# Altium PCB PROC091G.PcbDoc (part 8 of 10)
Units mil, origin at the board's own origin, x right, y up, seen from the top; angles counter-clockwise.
Board outline 4538.11 x 994.94 mil, 8 copper layers (Top Layer, GND1, Sig1, PWR1, PWR2, Sig2, GND2, Bottom Layer), stack 59.155 mil thick; 446 components, 329 nets, 5050 pads, 868 vias.
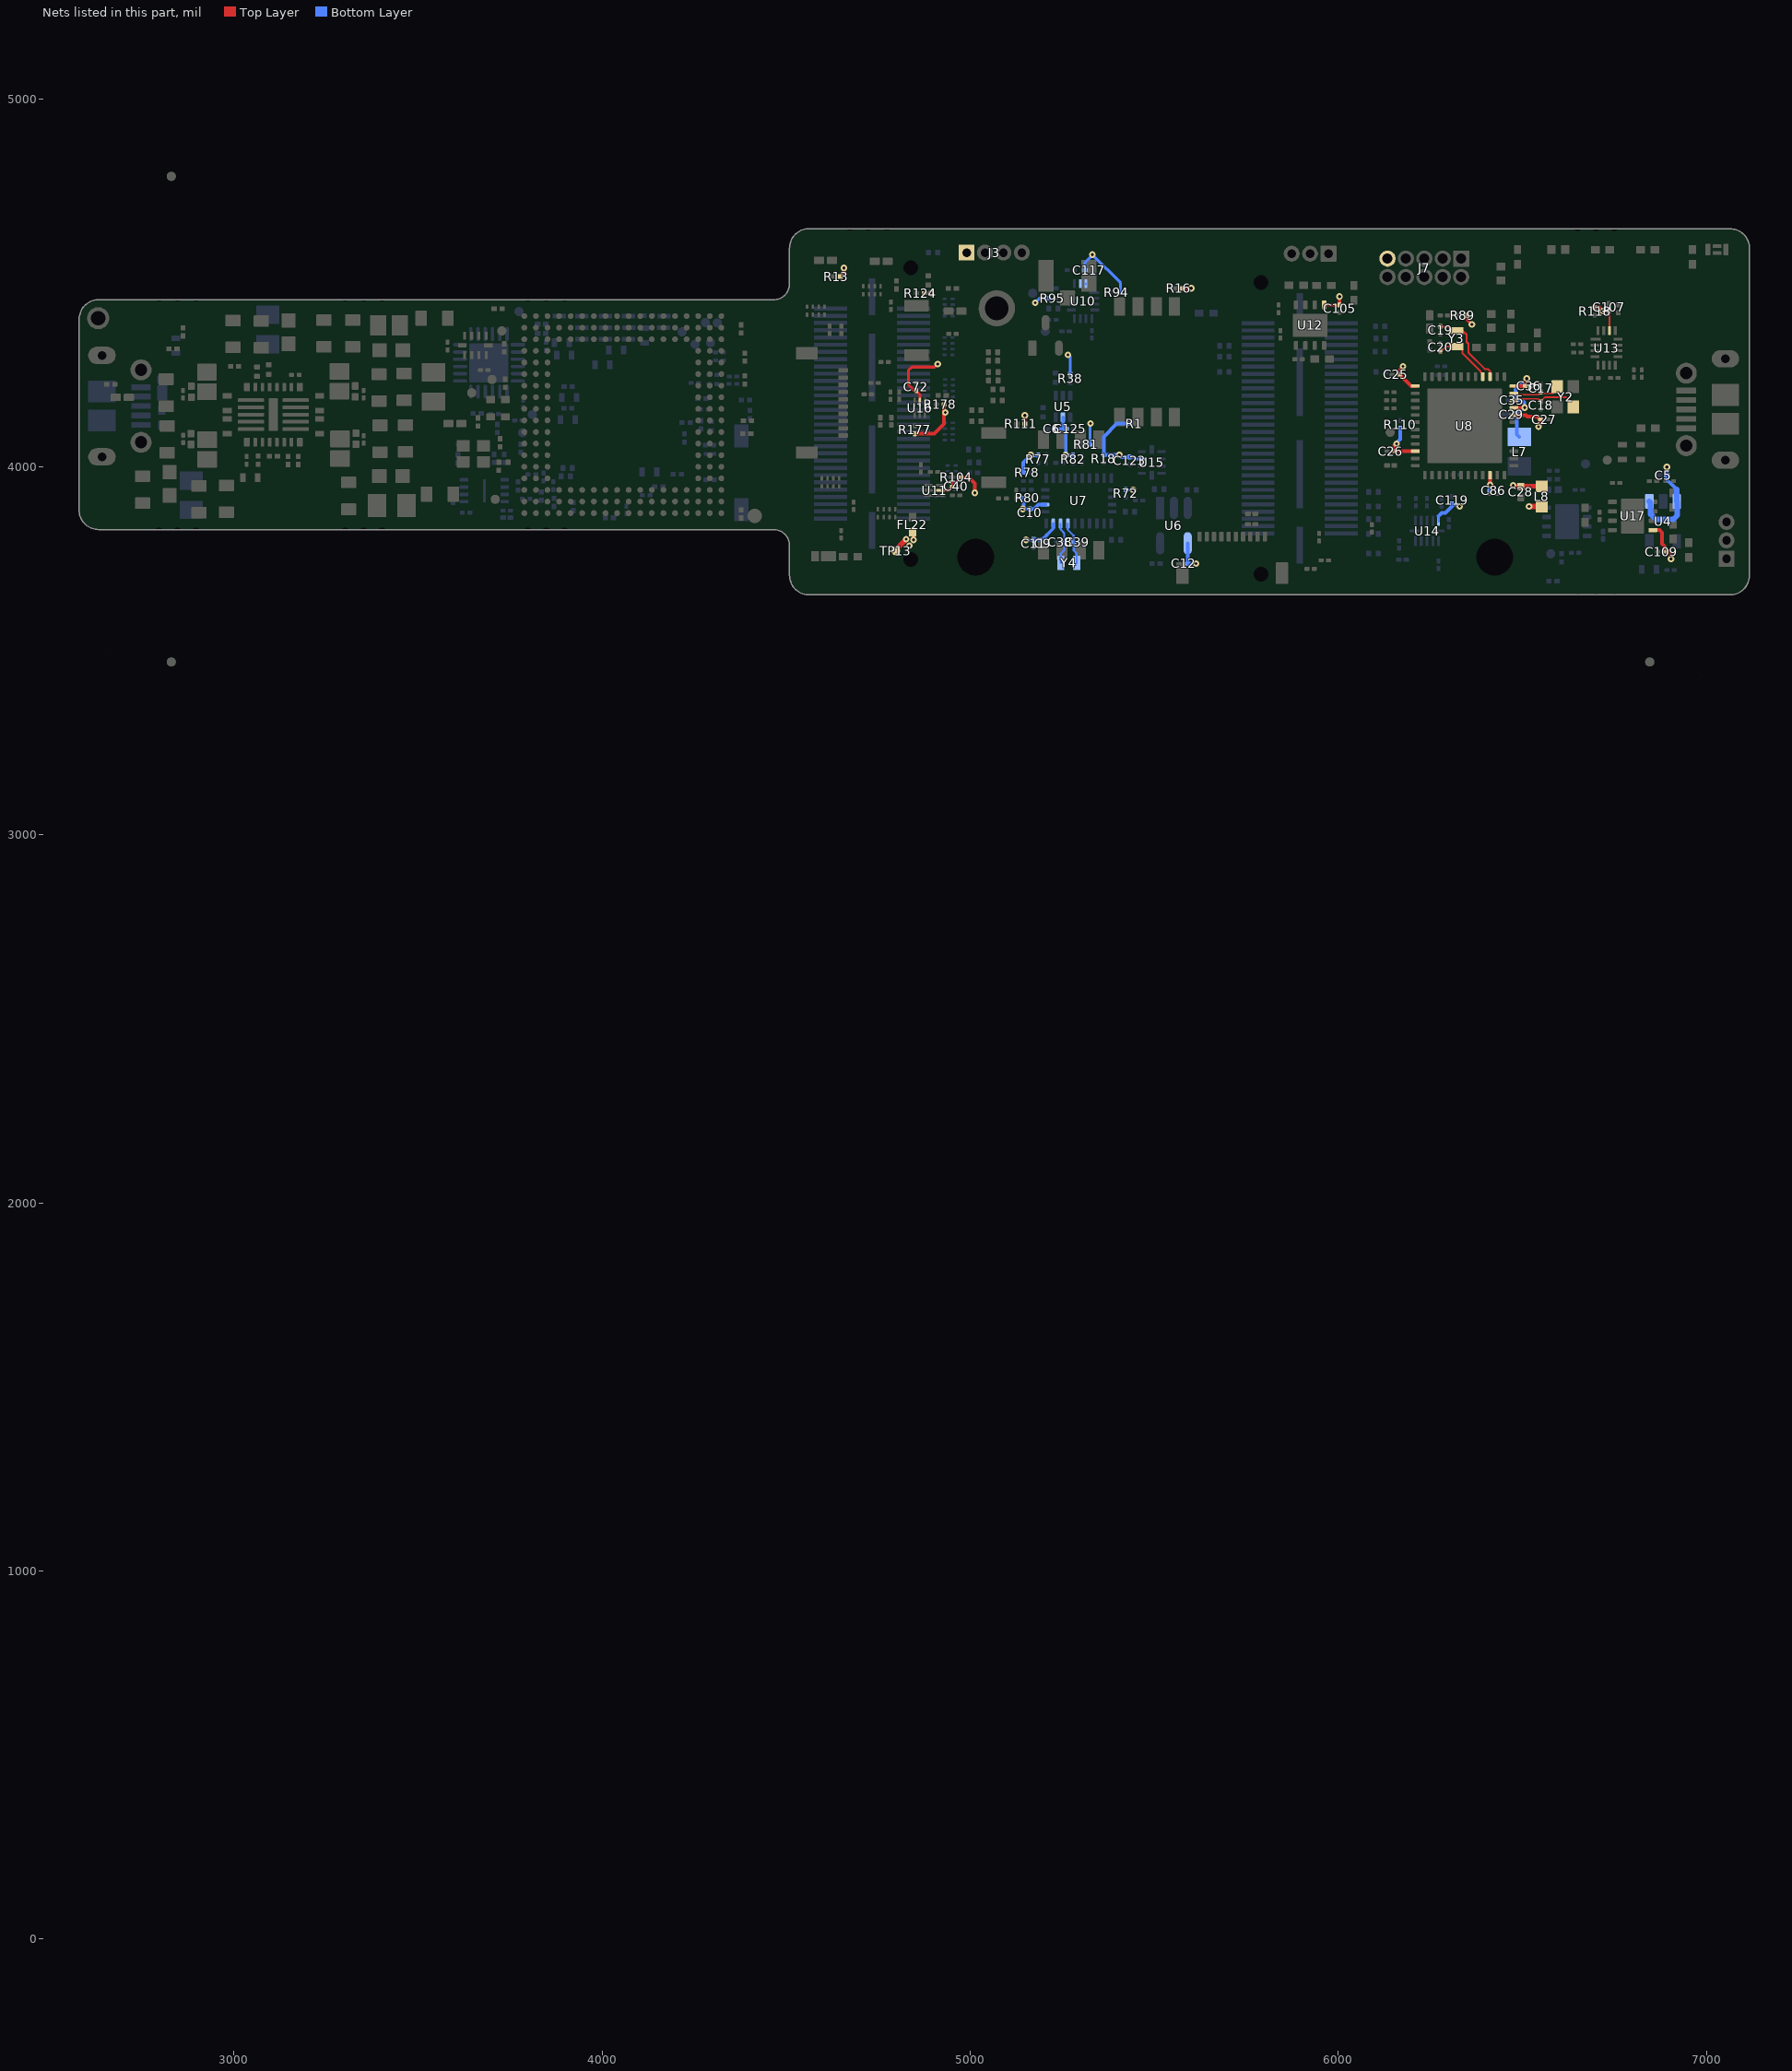
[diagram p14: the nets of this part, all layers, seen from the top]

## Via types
v1: diameter 18, hole 8, Top Layer to Bottom Layer, tented both sides, 832 vias
v2: diameter 19.68, hole 7.87, Top Layer to Bottom Layer, tented both sides, 34 vias
v3: diameter 17, hole 7.87, Top Layer to Bottom Layer, tented both sides, 1 vias
v4: diameter 17, hole 8, Top Layer to Bottom Layer, tented both sides, 1 vias

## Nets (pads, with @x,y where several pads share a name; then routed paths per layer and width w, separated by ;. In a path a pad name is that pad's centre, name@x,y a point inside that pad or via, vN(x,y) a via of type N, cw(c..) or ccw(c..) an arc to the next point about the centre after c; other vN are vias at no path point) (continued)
VCC_BA_3V3: C5.1 C6.2 C9.2 C10.2 C11.1 C12.2 C40.1 C72.2 C105.2 C107.1 C109.2 C117.1 C119.1 C123.1 C125.1 FL22.2 J3.1 J7.9 L8.1 R1.2 R13.1 R16.1 R18.1 R38.2 R72.1 R77.1 R78.1 R80.1 R81.1 R82.1 R89.2 R94.2 R95.2 R104.2 R111.2 R118.2 R124.2 R177.1 R178.1 TP13.1 U4.1 U4.3 U5.5 U6.4 U7.3 U7.28 U10.14 U10.15 U11.5 U12.5 U13.14 U14.11 U15.8 U16.5 U17.5 | length 2442.1
  Top Layer w5.5: v1(6718.6,4423.21) C107.1@6735.03,4423.21 6736.81,4421.43 U13.14@6736.81,4370
  Top Layer w6: U11.5@4920.42,3935.72 4941.34,3935.72 C40.1@4951.69,3946.07 4951.69,3954.47 4955.22,3957.99 4959.62,3957.99 4971.85,3970.22 R104.2@4971.85,3971.36
  Top Layer w8: U16.5@4863.37,4175.21 4863.37,4196.33 4853.37,4206.33 C72.2@4853.37,4207.46 4848.26,4207.46 4832.37,4223.35 4832.37,4262.14 4841.23,4271 4903.58,4271 v1(4911.71,4279.13) ; R124.2@4875.2,4471.7 4893.34,4471.7 v1(4893.63,4472) ; R111.2@5148.42,4116.46 5148.42,4139.35 v1(5148.55,4139.49) ; U12.5@5961.82,4439.58 5961.95,4439.45 C105.2@6003.52,4439.45 ; v1(6003.44,4462.27) 6003.44,4439.53 C105.2@6003.52,4439.45 ; C105.2@6003.64,4439.33 C105.2@6003.52,4439.45 ; R89.2@6349.22,4411.08 6349.22,4400.27 v1(6362.92,4386.56)
  Top Layer w10: R13.1@4647.44,4516.76 4657.26,4526.58 4657.11,4526.73 v1(4657.11,4540) ; v1(4846.16,3801.37) FL22.2@4846.16,3821.15 ; R177.1@4849.59,4089.43 4901.92,4089.43 4928.74,4116.25 4928.74,4143.73 v1(4932.61,4147.6) 4929.21,4151 R178.1@4929.21,4169.46 ; R104.2@4971.85,3971.36 4996.14,3971.36 5013.06,3954.44 5013.06,3929.27 v1(5012.81,3929.02) ; R16.1@5577.42,4484.46 5600.32,4484.46 v1(5600.59,4484.74) ; R118.2@6696.81,4432.52 6709.29,4432.52 v1(6718.6,4423.21) ; U17.5@6854.9,3827.61 6873.17,3827.61 6879.78,3821 6879.78,3790.43 6887.42,3782.79 C109.2@6887.42,3768.9 6897.81,3768.9 6903.81,3762.9 v1(6903.81,3749)
  Top Layer w15: TP13.1@4798.18,3771.83 4798.18,3774.39 4825.79,3802 v1(4825.78,3803.31) ; v1@6518.19,3891.83 L8.1@6552.57,3891.83
  Bottom Layer w5.5: C11.1@5172.1,3801.28 C11.1@5172.24,3801.43 ; C9.2@5196.95,3801.43 C9.2@5197.1,3801.57 C9.2@5197.1,3803.37 ; C123.1@5432.91,4026.38 C123.1@5433.48,4025.82
  Bottom Layer w6: U14.11@6272.54,3850.95 U14.11@6272.54,3866.08
  Bottom Layer w8: v1(5176.77,4445.78) 5176.77,4446.49 5188.17,4457.88 5212.69,4457.88 R95.2@5212.97,4457.6 ; 5207.55,3813.82 5225.98,3832.25 U7.28@5225.98,3845.7 ; C6.2@5231.03,4103.02 5231.08,4102.96 C125.1@5258.96,4102.96 ; U5.5@5251.98,4134.63 5252.48,4134.13 5252.48,4109.45 C125.1@5258.96,4102.96 ; v1(5259.36,4031.52) 5260.09,4032.25 5260.09,4102.17 C125.1@5260.82,4102.9 5259.02,4102.9 C125.1@5258.96,4102.96 ; v1(5265.93,4303.71) 5266.11,4303.52 5266.66,4303.52 5272,4298.18 R38.2@5272,4251.02 ; C117.1@5311.99,4534 5311.99,4555.25 5330.91,4574.18 5333.82,4574.18 5408.52,4499.49 R94.2@5408.52,4473.91 ; U10.15@5314.61,4497.04 U10.15@5314.67,4496.97 ; R81.1@5325.76,4059.87 5325.76,4116.22 v1(5326.65,4117.12) ; R72.1@5422.76,3937.25 5422.88,3937.13 5442.81,3937.13 v1(5442.93,3937) ; C123.1@5433.48,4025.82 5446.33,4025.82 5450.78,4021.37 U15.8@5466.7,4021.37
  Bottom Layer w10: R78.1@5144.48,3984 5144.48,4011.07 v1(5164.93,4031.52) R77.1@5185.3,4031.52 ; R80.1@5144.96,3915 5144.96,3887.63 v1(5142.51,3885.18) C10.2@5162.69,3885.18 5172.71,3885.18 5184.9,3897.38 U7.3@5203.84,3897.38 ; v1(5151.93,3801.28) C11.1@5172.1,3801.28 ; C11.1@5172.24,3801.43 C9.2@5196.95,3801.43 ; C9.2@5197.1,3803.37 5207.55,3813.82 ; v1(5259.36,4031.52) R82.1@5279.72,4031.52 ; C123.1@5432.91,4026.38 5411.3,4026.38 v1(5405.37,4032.31) R18.1@5362.78,4032.31 5362.78,4081.15 5398.61,4116.98 R1.2@5434.34,4116.98 ; U6.4@5590.94,3792.16 C12.2@5590.94,3737.11 v1(5613.91,3737.11) ; U14.11@6272.54,3866.08 6280.92,3874.46 6291.27,3874.46 6308.91,3892.1 C119.1@6308.91,3897.4 ; C119.1@6308.91,3899.2 C119.1@6308.91,3897.4 ; v1(6330.1,3892.41) 6327.93,3892.41 6323.12,3897.23 6309.09,3897.23 C119.1@6308.91,3897.4 ; v1(6892.81,3999) 6892.68,3998.87 C5.1@6892.68,3977 6892.68,3964.9 6919.58,3938
  Bottom Layer w15: U4.1@6844.78,3905.76 6848.43,3902.11 6848.43,3871.38 6862.81,3857 6909.81,3857 6920.81,3868 6920.81,3904.53 U4.3@6919.58,3905.76 6919.58,3938
  other v1: 4835,3786 6518.19,3892.23 5331.6,4576.41
VDDR: C29.1 C35.1 C36.1 L7.2 U8.45 U8.48 | length 283.2
  Top Layer w10: U8.45@6477.24,4160.32 6477.31,4160.39 6506.11,4160.39 v1(6506.18,4160.46) ; U8.48@6477.24,4219.38 C36.1@6508.24,4219.38 6508.24,4235.42 v1(6512.18,4239.36)
  Bottom Layer w10: L7.2@6491.96,4080.83 6485.09,4087.71 C29.1@6485.09,4142.46 v1@6504.62,4161.99 ; v1@6504.65,4161.99 6504.65,4174.43 6498,4181.08 6481.54,4181.08 C35.1@6481.36,4181.25 6481.36,4208.55 v1(6512.18,4239.36)
VDDS: C25.1 C26.1 C27.1 C28.1 C86.1 L8.2 R110.2 U8.13 U8.22 U8.34 U8.44 | length 415.1
  Top Layer w10: v1@6157.19,4062.2 6152.19,4057.2 C26.1@6152.19,4042.21 U8.22@6209.52,4042.21 ; v1(6176.16,4272.45) 6166.96,4263.26 C25.1@6166.96,4250.28 6197.87,4219.38 U8.13@6209.52,4219.38 ; v1(6412.28,3950.73) U8.34@6412.28,3977.25 ; U8.44@6477.24,4140.64 6477.41,4140.46 6510.65,4140.46 6514.37,4136.74 6539.1,4136.74 6547.37,4128.46 C27.1@6549.17,4128.46 ; L8.2@6540.11,3947.02 L8.2@6540.18,3946.95 ; v1(6544.18,4108.46) 6549.18,4113.46 C27.1@6549.17,4128.46
  Top Layer w12: v1(6474.93,3949.86) 6478.54,3946.25 C28.1@6495.93,3946.25 6496.63,3946.95 L8.2@6540.18,3946.95
  Bottom Layer w10: v1(6158.08,4062.2) 6158.08,4064.36 6168.27,4074.55 R110.2@6168.27,4104.23 ; C86.1@6412.25,3935.35 v1@6412.25,3950.7
X32K_Q1: C19.1 U8.3 Y3.1 | length 225
  Top Layer w5.5: C19.1@6277.6,4380.71 6298.4,4380.71 6309.53,4369.58 Y3.1@6320.71,4369.58 6338.05,4369.58 6348.65,4358.98 6348.65,4339.08 6353.86,4333.87 6353.86,4309.95 6398.28,4265.53 6406.19,4265.53 6412.28,4259.44 U8.3@6412.28,4244.97
X32K_Q2: C20.1 U8.4 Y3.2 | length 164.4
  Top Layer w5.5: C20.1@6277.6,4315.14 6281.45,4315.14 6292.58,4326.27 Y3.2@6320.71,4326.27 6330.35,4326.27 6337.44,4319.18 6337.44,4308.18 6386.38,4259.24 6386.38,4258.26 6392.59,4252.05 U8.4@6392.59,4244.97
X48M_N: C18.1 U8.46 Y2.3 | length 187.6
  Top Layer w4: U8.46@6477.24,4180.01 6484.32,4180.01 6488.67,4184.35 6520.25,4184.35 6543.03,4184.35 C18.1@6550.62,4176.76 6550.62,4178.56 6560.91,4188.85 6619.47,4188.85 6638.36,4169.96 Y2.3@6638.36,4162.29
X48M_P: C17.1 U8.47 Y2.1 | length 140
  Top Layer w4: U8.47@6477.24,4199.69 6484.32,4199.69 6488.67,4195.35 6524.81,4195.35 6543.03,4195.35 6545.64,4197.96 6547.44,4197.96 6550.62,4201.13 C17.1@6550.62,4202.93 6553.69,4199.85 6585.17,4199.85 Y2.1@6602.73,4217.41
XIN32: C38.1 U7.27 Y4.1 | length 114.6
  Bottom Layer w5.5: U7.27@5245.67,3845.7 5245.67,3829.74 5253.47,3821.93 5253.47,3821.52 5255.25,3819.74 C38.1@5255.25,3795.56 5255.25,3772.96 5246.17,3763.87 Y4.1@5246.17,3738.88
XOUT32: C39.1 U7.26 Y4.2 | length 117.1
  Bottom Layer w5.5: U7.26@5265.35,3845.7 5264.97,3845.33 5264.97,3829.17 5281.32,3812.82 C39.1@5281.32,3795.56 5281.32,3772.24 5289.47,3764.09 Y4.2@5289.47,3738.88
pads on no net: A1.2-3 A1.5-6 Designator1. Designator1_2. Designator2. Designator2_1. Designator3. Designator3_1. Designator4. Designator4_1. Designator5. Designator5_1. Designator6. Designator7. Designator10. Designator11. Designator22_1. Designator23. FID1.1 FID2.1 FID3.1 FID4.1 FID5.1 FID6.1 J1.4 J2.1 J2.3 J2.4 J2.5 J2.6 J2.7 J2.9 J2.MH1 J2.MH2 J4.4 J5.2 J5.3 J5.4 J6.4 J9.2@5205.06,4518.36 J9.3@5323.17,4518.36 J11.4 J11.5 J11.6 J11.8 J11.14 J11.20 J11.22 J11.32 J11.34 J11.35 J11.37 J11.38 J11.39 J11.40 J11.41 J11.43 J11.45 J11.47 J11.49 J11.MH1 J11.MH2 RA2.1 RA2.8 RA5.4 RA5.5 S2.4 S2.5 U1. U2.A3 U2.A4 U2.B3 U2.B4 U2.B5 U2.C3 U2.C4 U2.C5 U3.10 U3.11 U3.14 U3.15 U3.16 U3.18 U3.19 U3.21 U3.22 U3.23 U3.24 U7.1 U7.7 U7.8 U7.12 U7.13 U7.15 U7.16 U7.18 U7.21 U7.22 U7.23 U7.24 U8.5 U8.6 U8.9 U8.10 U8.12 U8.18 U8.19 U8.20 U8.28 U8.32 U8.36 U8.37 U8.38 U8.39 U8.40 U8.41 U8.42 U8.43 U12.9@5898.44,4384.46 U12.9@5948.44,4384.46 U17.9@6799.78,3841 U17.9@6799.78,3891 U19.9@6621.18,3825.66 U19.9@6621.18,3875.27

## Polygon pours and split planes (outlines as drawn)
GND on Top Layer " " (solid, remove dead copper, pour order 543): 4402.88,4248.39 4391.58,4259.69 4391.58,4271.84 4402.88,4282.59 4402.88,4641.74 6325.94,4641.74 6325.94,4219.37 6620.81,4219.38 6620.81,4496.76 6980.54,4496.76 6980.54,4323.67 7112.08,4323.67 7112.08,3657.14 4402.88,3657.14
GND on Top Layer " " (solid, remove dead copper, pour order 577): 6979.95,4641.37 6979.95,4515.96 6600.52,4515.97 6600.52,4279.33 6357.55,4279.33 6357.55,4641.29
GND on Top Layer "Top Layer-GND" (solid, remove dead copper, pour order 701): 3597.2,4404.84 3615.25,4422.89 3615.25,4439.59 3609.93,4444.91 3565.65,4444.91 3565.65,4381.29 3595.67,4381.29 3597.2,4382.82
GND on Top Layer " " (solid, remove dead copper, pour order 633): 2866.76,4108.87 2874.44,4116.56 2883.51,4116.22 2948.98,4116.22 2955.77,4123.01 2994.86,4123.01 2995.98,4124.13 2995.98,4158.09 2991.86,4160.15 2899.44,4160.15 2889.5,4170.1 2871.02,4170.1 2866.76,4174.36 2866.76,4189.01 2801.59,4189.01 2782.68,4170.1 2782.68,4098.35 2801.42,4079.6 2866.33,4079.6 2866.76,4080.03
5V_IN on Top Layer "Bottom Layer-5V_IN 2" (solid, remove dead copper, pour order 587): 2998.13,4224.17 2960.5,4224.17 2960.5,4187.61 2962.5,4185.61 2998.13,4185.61
GND on Top Layer " " (solid, remove dead copper, pour order 635): 3417.49,4130.49 3417.49,4195.36 3372.89,4195.36 3369.75,4192.23 3348.49,4192.23 3345.91,4189.65 3345.91,4175.13 3340.07,4169.1 3275.05,4169.1 3266.17,4160.21 3219.14,4160.21 3218.02,4159.09 3218.02,4125.13 3220.26,4124.01 3263.33,4124.01 3273.45,4113.88 3339.9,4113.88 3345.64,4108.14 3345.63,4097.36 3352.4,4090.59 3363.18,4090.59 3410.14,4090.6 3417.49,4097.95
5V_IN on Top Layer " " (solid, remove dead copper, pour order 691): 2779.39,4264.53 2830.94,4264.53 2830.94,4335.73 2781.37,4335.73 2779.39,4333.75 2779.39,4294.36
GND on Top Layer " " (solid, remove dead copper, pour order 631): 2948.3,4303.91 3012.75,4303.91 3015.52,4306.68 3050.61,4306.68 3098.31,4306.68 3098.31,4349.1 2948.3,4349.1
AR_1P0_RF1 on Top Layer " " (solid, remove dead copper, pour order 629): 2956.83,4359.24 2967.26,4369.67 2977.04,4379.45 3172.04,4379.01 3172.04,4442.78 2908.04,4442.78 2908.04,4359.24
GND on Top Layer " " (solid, remove dead copper, pour order 627): 3252.02,3911.78 3334.07,3911.78 3348.09,3925.8 3405.82,3925.8 3405.82,3847.12 3252.02,3847.12
GND on Top Layer " " (solid, remove dead copper, pour order 625): 3576.89,3846.43 3576.89,3957.14 3680.11,3957.14 3680.11,3846.43
GND on Top Layer " " (solid, remove dead copper, pour order 623): 2780.72,3920.28 2780.72,3861.72 2668.39,3861.72 2668.39,3920.28
GND on Top Layer " " (solid, remove dead copper, pour order 619): 3224.95,4366.9 3224.95,4448.76 3343.03,4448.76 3343.03,4366.9
GND on Top Layer " " (solid, remove dead copper, pour order 615): 3487.96,4096.85 3446.03,4096.85 3441.58,4101.3 3441.58,4202.49 3574.18,4202.49 3574.18,4151.65 3523.34,4151.65 3487.96,4116.27
AR_1V8 on Top Layer " " (solid, remove dead copper, pour order 611): 3552.4,4009.13 3541.3,4020.23 3541.3,4052.85 3532.25,4062.09 3437.43,4062.09 3437.43,3865.59 3549.82,3865.59 3552.4,3863
GND on Top Layer " " (solid, remove dead copper, pour order 609): 2964.45,3989.38 2952.64,3977.57 2883.43,3977.57 2883.43,3927.37 3002.05,3927.37 3008.75,3934.07 3008.75,3989.38
AR_1P2 on Top Layer " " (solid, remove dead copper, pour order 607): 2851.91,3913.94 2851.91,3934.9 2843.33,3943.48 2807.29,3943.48 2803.46,3939.65 2803.46,3916 2803.03,3856.92 2817.21,3842.73 3097.77,3842.73 3097.77,3894.63 2871.23,3894.63
PMIC_1V8 on Top Layer " " (solid, remove dead copper, pour order 605): 3253.84,4044.28 3253.84,3978 3290.63,3941.58 3418.8,3941.58 3418.8,4059.29 3376.76,4059.29 3362.24,4044.77
AR_1P0_RF2 on Top Layer " " (solid, remove dead copper, pour order 601): 3442.32,4334.13 3442.32,4344.49 3429.9,4356.91 3429.9,4416.61 3441.33,4428.03 3521.74,4428.03 3525.88,4423.99 3525.88,4397.42 3558.72,4364.58 3558.72,4306.15 3573.78,4291.61 3573.78,4231.58 3508.35,4231.58 3502.16,4237.77 3442.28,4237.77 3442.32,4238.36
PMIC_1V0 on Top Layer " " (solid, remove dead copper, pour order 597): 3124.76,4309.57 3149.4,4284.94 3151.17,4284.94 3177.58,4284.94 3216.54,4284.94 3261.32,4240.16 3261.32,4237.18 3414.48,4237.29 3414.48,4335.8 3414.48,4412.32 3369.74,4412.32 3369.74,4359.63 3353.43,4343.32 3340.14,4343.32 3194.18,4343.32 3184.05,4352.73 3126.64,4352.73 3124.76,4350.85 3124.76,4343.32
PMIC_3V3 on Top Layer " " (solid, remove dead copper, pour order 595): 2953.21,4277.32 2953.21,4234.69 2868.78,4234.69 2847.45,4213.36 2797.4,4213.36 2791.17,4219.6 2791.17,4254.19 2833.09,4254.19 2864.73,4285.82 2864.73,4327.73 2932.58,4327.73 2932.57,4297.95
PMIC_1V2 on Top Layer " " (solid, remove dead copper, pour order 593): 2954.43,4042.19 2954.43,3995.93 2885.68,3995.93 2856.48,3966.74 2792.36,3966.74 2776.28,3950.65 2737.67,3950.65 2728.23,3960.09 2728.23,3966.74 2728.23,4027.91 2775.25,4027.91 2802.47,4055.14 2849.27,4055.14 2862.22,4042.19
VCC_BA_3V3 on Top Layer "TOP-VCC_BA_3V3" (solid, remove dead copper, pour order 194): 4830.39,3829.83 4860.96,3829.83 4860.96,3775.05 4859.25,3773.34 4827.36,3773.34 4814.82,3785.87 4814.82,3822.44 4822.21,3829.83
USB_5V_B on Top Layer "Top Layer-USB_5V_B" (solid, remove dead copper, pour order 541): 6978.75,4091.96 6983.75,4096.96 6983.75,4108.96 6977.75,4114.96 6910.67,4114.96 6903.17,4122.46 6886.64,4138.99 6845.74,4138.99 6845.74,4113.96 6845.74,4095.5 6845.74,4067.38 6890.47,4067.38 6900.31,4080.03 6912.24,4091.96
5V_IN_SW on Top Layer "TOP-5V_IN_SW" (solid, remove dead copper, pour order 184): 4680.99,3786.45 4734.41,3786.45 4766.02,3754.84 4766.02,3678.12 4680.99,3678.12
PMIC_3V3 on Top Layer "TOP-PMICOUT_3V3" (solid, remove dead copper, pour order 332): 4858.29,3846.65 4858.29,3928.41 4858.29,3946.33 4808.29,3996.33 4773.82,3996.33 4767,3989.51 4767,3934.57 4808.29,3893.28 4808.29,3853.17 4814.8,3846.65
RE on Top Layer "Bottom Layer-RE" (solid, remove dead copper, pour order 166): 7076.12,4438.37 7052.5,4438.37 7052.5,4627.35 7076.12,4627.35
no net on Top Layer " " (solid, remove dead copper, pour order 446): 6030.79,4320.34
5V_IN_B on Top Layer "Top Layer-5V_IN_B" (solid, remove dead copper, pour order 495): 6710.21,4144.21 6838.21,4144.21 6838.21,4045.97 6710.21,4045.97
no net on Top Layer "Top Layer-No Net" (solid, remove dead copper, pour order 489): 6335,4190
PMIC_3V3 on Top Layer " " (solid, remove dead copper, pour order 463): 4333.76,4153.15 4380.42,4153.15 4392.49,4141.09 4392.49,4117.8 4344.94,4117.8 4327.78,4134.97 4327.78,4146.94 4333.32,4152.48
GND on Top Layer " " (solid, remove dead copper, pour order 461): 4193.96,4266.52 3921,4266.52 3921,4014.47 4193.96,4014.47
5V_IN on Top Layer "TOP-5V_IN 1" (solid, remove dead copper, pour order 186): 4524.69,3777.41 4588.97,3777.41 4588.97,3679.21 4524.69,3679.21
NetD2_2 on Top Layer "TOP-NetD2_2" (solid, remove dead copper, pour order 182): 4600.58,3789.43 4668.11,3789.43 4668.11,3681.34 4600.58,3681.34
no net on Top Layer "TOP-No Net 2" (solid, remove dead copper, pour order 334): 6159.44,4021.48
no net on Top Layer "TOP-No Net" (solid, remove dead copper, pour order 180): 6163.15,4205.41
AR_1P0_RF2 on Bottom Layer " " (solid, remove dead copper, pour order 687): 4002.3,4262.65 4002.3,4434.54 3979.83,4434.54 3973.82,4434.54 3948.08,4434.64 3948.08,4347.22 3902.1,4347.22 3902.1,4288.23 3902.1,4262.64
GND on Bottom Layer " " (solid, remove dead copper, pour order 573): 6591.69,3656.75 6591.69,3678.82 6516.78,3678.82 6494.78,3656.75 4401.64,3656.75 4401.64,4641.74 6974.71,4641.74 6974.71,4298.45 7112.08,4298.45 7112.08,3656.75
PMIC_3V3 on Bottom Layer "Bottom Layer-PMICOUT_3V3" (solid, remove dead copper, pour order 454): 3973.66,3945.37 3982.27,3936.76 3982.28,3886.75 3996.06,3872.97 4015.6,3872.97 4015.6,3844.59 3954.73,3844.59 3934.18,3865.14 3934.18,3915.38 3889.79,3915.38 3882.16,3907.75 3857.31,3907.75 3842.3,3922.76 3794.48,3922.76 3794.48,3968.8 3849.6,3968.8 3849.6,3945.37
GND on Bottom Layer " " (solid, remove dead copper, pour order 647): 2788.04,4340.02 2872.26,4340.02 2872.26,4413.91 2806.29,4413.91 2788.04,4395.66
GND on Bottom Layer "TOP-GND 1" (solid, remove dead copper, pour order 452): 2775.23,4248.71 2775.23,4448.76 2596.38,4448.76 2596.38,3991.45 2620.02,3967.81 2803.75,3967.81 2815.08,3979.14 2815.08,4092.57 2697.52,4092.57 2685.56,4104.54 2685.56,4154.46 2685.56,4243.98 2691.94,4250.83 2716.88,4250.83 2727.4,4240.31 2766.84,4240.31
GND on Bottom Layer "Bottom Layer-GND 2" (solid, remove dead copper, pour order 699): 3416.4,4266.78 3335.29,4347.89 3335.29,4444.39 3195.18,4444.39 3178.78,4427.98 3178.78,4322.7 3147.52,4291.45 3051.57,4195.5 2845.25,4195.5 2845.25,4083.08 2867.85,4060.48 2977.88,4060.48 3033.13,4005.22 3076.36,3961.99 3143.21,3961.99 3285.68,3961.99 3416.4,4089.18
AR_1P0_RF1 on Bottom Layer " " (solid, remove dead copper, pour order 643): 2887.85,4359.04 2956.69,4358.89 2977.42,4379.62 3130.58,4379.62 3130.59,4441.54 2893.66,4441.54 2887.85,4435.73
AR_1V8 on Bottom Layer "BOTTOM-AR_1V8" (solid, remove dead copper, pour order 669): 3915.56,4106.49 3936.13,4106.49 3936.13,4094.67 4027.05,4003.76 4117.79,4003.76 4117.79,3969.2 3969.04,3969.2 3906.98,4031.26 3877.1,4061.14 3877.1,4115.29 3858.83,4115.29 3841.37,4132.76 3841.37,4145.76 3834.37,4152.76 3823.37,4152.76 3823.37,4184.76 3815,4184.76 3815,4324 3857.74,4324 3857.74,4292.99 3865.06,4285.68 3873.32,4285.68 3876,4282.72 3876,4231 3904.31,4231 3904.31,4214.09 3904,4206.74 3904,4166.83 3904,4126.8 3904,4118.05
5V_IN on Bottom Layer " " (solid, remove dead copper, pour order 661): 2864.39,4252.36 2842.82,4228.87 2784.47,4228.87 2784.47,4319.47 2787.2,4322.2 2864.39,4322.2
GND on Bottom Layer " " (solid, remove dead copper, pour order 645): 3054.42,4312.42 3059.18,4307.66 3130.21,4307.66 3130.21,4358.53 2986.47,4358.53 2975.02,4347.08 2946.17,4347.08 2946.57,4303.49 2965.55,4303.49 2974.48,4312.42
GND on Bottom Layer " " (solid, remove dead copper, pour order 641): 2848.49,4008.35 2848.49,3926.98 2977.95,3926.98 2977.95,4008.35
AR_1P2 on Bottom Layer " " (solid, remove dead copper, pour order 639): 2845.29,3907.36 3000.37,3907.36 3016.05,3923.03 3100.56,3923.03 3100.56,3841.4 2845.29,3841.4
5V_IN on Bottom Layer " " (solid, remove dead copper, pour order 637): 2953.62,4053.74
GND on Bottom Layer "BOTTOM-GND 1" (solid, remove dead copper, pour order 250): 3946.37,4124.5 3949.6,4121.26 3962.92,4121.26 3965.22,4121.27 3971.54,4114.95 3971.54,4089.54 4044.79,4016.28 4203.3,4016.28 4203.3,4099.8 4209.2,4105.7 4223.9,4105.7 4227.1,4108.9 4227.1,4228.46 3946.37,4228.46
AR_1V8 on Bottom Layer "Bottom Layer-BB_1V8" (solid, remove dead copper, pour order 372): 4129.35,4407.73 4135.08,4402.01 4135.08,4354.75 4131.17,4350.83 4103.27,4350.83 4103.27,4328.02 4162.87,4328.02 4162.87,4434.77 4129.35,4434.77
VCC_BA_3V3 on Bottom Layer "Bottom Layer-VCC_BA_3V3" (solid, remove dead copper, pour order 208): 5293.97,4513.38 5303.87,4523.29 5303.87,4544 5319.75,4544 5319.75,4483.01 5293.97,4483.01
NetFL4_1 on Bottom Layer "Bottom Layer-NetFL4_1" (solid, remove dead copper, pour order 212): 5641.08,4365 6104.93,4365 6104.93,4541.57 5641.08,4541.57
5V_HD_IN on Bottom Layer "Bottom Layer-5V_HD_IN 1" (solid, remove dead copper, pour order 563): 6641.93,3812.08 6641.93,3696.21 6707.53,3696.21 6707.53,3812.08 6702.57,3812.08 6659.82,3812.08 6662.84,3812.08
5V_HD_IN on Bottom Layer "Bottom Layer-5V_HD_IN 2" (solid, remove dead copper, pour order 571): 4801.46,3858.62 4801.49,3866.78 4945.6,3866.78 4945.6,3853.99 4906.69,3815.09 4906.69,3808.39 4901.95,3793.71 4895.93,3774 4895.95,3758.16 4861.97,3758.16 4861.97,3814.66 4801.46,3815.09
5V_HD_IN on Bottom Layer "Bottom Layer-5V_HD_IN 3" (solid, remove dead copper, pour order 569): 4868.09,3859.51
5V_IN_B on Bottom Layer "Bottom Layer-5V_IN_B" (solid, remove dead copper, pour order 557): 6653.01,3852.6 6759.98,3852.6 6759.98,4006.83 6775.86,4022.71 6798.1,4022.71 6798.1,4150.17 6690.11,4150.17 6690.11,4110.05 6690.85,4109.3 6690.85,4101.69 6690.85,4075.96 6690.86,4067.7 6655.23,4032.07 6655.23,3923.83 6657.56,3921.5 6658.81,3920.25 6675.91,3903.15 6685.85,3893.21 6685.75,3876.47 6681.98,3872.7 6653.01,3872.7
5V_HD_IN on Bottom Layer "Bottom Layer-5V_HD_IN" (solid, remove dead copper, pour order 210): 5569.44,4438.76 5640.18,4438.76 5640.18,4309.18 5567.97,4309.18
RE on Bottom Layer "Bottom Layer-RE" (solid, remove dead copper, pour order 521): 7076.12,4438.37 7052.5,4438.37 7052.5,4627.35 7076.12,4627.35
5V_IN_SW on Bottom Layer "BOTTOM-5V_IN_SW" (solid, remove dead copper, pour order 322): 6716.51,3843.31 6664.37,3843.31 6664.37,3827.48 6697.27,3827.48 6706.84,3817.91 6713.65,3817.91 6727.01,3817.91 6727.01,3728.16 6799.26,3728.16 6826.37,3755.28 6826.37,3800.18 6821.37,3805.18 6801.37,3805.18 6782.49,3805.18 6777.74,3809.92 6777.74,3842.18 6773.37,3846.18 6719.37,3846.18
GND on Bottom Layer " " (solid, remove dead copper, pour order 505): 3926.42,4354.12 3927.43,4353.11 3927.43,4346.38 3941.68,4346.38 3941.69,4434.66 3857.67,4434.66 3857.67,4356.47 3845.29,4344.09 3845.29,4328.08 3846.51,4326.86 3862.3,4326.86 3869.18,4319.97 3869.18,4293.11 3870.15,4292.14 3889.38,4292.14 3889.38,4338.92 3904.58,4354.12
GND on Bottom Layer "Bottom Layer-GND" (solid, remove dead copper, pour order 499): 4097.16,4341.2 4097.16,4362.67 4104.88,4370.38 4126.97,4370.38 4126.97,4399.57 4123.42,4403.12 4122.79,4434.87 4076.41,4434.87 4076.38,4341.2
GND on Bottom Layer "Bottom Layer-GND 1" (solid, remove dead copper, pour order 483): 4039.05,4265.4 4039.05,4433.84 4013.12,4433.84 4013.07,4265.4
no net on Bottom Layer " " (solid, remove dead copper, pour order 475): 4514.15,4464.37
no net on Bottom Layer " " (solid, remove dead copper, pour order 440): 3587.57,4371.27
no net on Bottom Layer " " (solid, remove dead copper, pour order 434): 3587.57,4371.27
NetD1_2 on Bottom Layer "Bottom Layer-NetD1_2" (solid, remove dead copper, pour order 398): 2783.82,4138.73 2783.82,4218.49 2829.97,4218.49 2829.97,4138.73
USB_5V on Bottom Layer "Bottom Layer-USB_5V" (solid, remove dead copper, pour order 374): 2718.37,4122.78 2760.91,4122.78 2765.05,4126.93 2826.65,4126.93 2826.65,4086.12 2775.03,4086.12 2762.36,4098.78 2718.37,4098.78
AR_1P0_RF1 on Bottom Layer "Bottom Layer-AR_1P0_RF1" (solid, remove dead copper, pour order 324): 4143.75,4265.66 4143.75,4315.28 4087.72,4315.28 4069.71,4333.41 4069.71,4434.87 4047.32,4434.87 4047.32,4265.66
no net on Bottom Layer "BOTTOM-No Net 3" (solid, remove dead copper, pour order 318): 4918.91,3816.49
no net on Bottom Layer "BOTTOM-No Net 4" (solid, remove dead copper, pour order 266): 4983.76,3878.78
no net on Bottom Layer "BOTTOM-No Net" (solid, remove dead copper, pour order 264): 4304.65,4371.57
no net on Bottom Layer "BOTTOM-No Net 1" (solid, remove dead copper, pour order 262): 4033.37,4452.75
AR_1P0_RF2 on PWR1 " " (solid, remove dead copper, pour order 649): 3472.99,4440.75 4009.12,4440.75 4009.12,4207.78 3472.99,4207.78
AR_1P0_RF1 on PWR1 " " (solid, remove dead copper, pour order 653): 3064.59,4050.45 3009.81,4105.58 2860.58,4105.58 2860.58,4436.21 3432.2,4436.21 3432.2,4187.06 4025.62,4187.06 4025.62,4419.23 4051.53,4445.14 4229.37,4445.14 4229.37,4050.45
AR_1P2 on PWR1 " " (solid, remove dead copper, pour order 663): 3004.46,3982.55 3064.38,4042.47 4261.24,4042.47 4261.24,4431.29 4278.49,4448.54 4413.48,4448.54 4422.39,4439.62 4422.39,3841.29 3004.46,3841.29
5V_HD_IN on PWR1 "PWR1-5V_HD_IN" (solid, remove dead copper, pour order 366): 5533.8,4375.58 5690.72,4375.58 5937.37,4131.32 6523.29,4131.32 6712,3942.62 6712,3657.14 4801.12,3657.14 4801.12,4038.88 5197.1,4038.88
5V_IN on PWR1 " " (solid, remove dead copper, pour order 364): 5124.64,4379.61 5261.18,4516.16 5837.01,4516.16 5973.56,4379.61 6028.31,4324.85 6104.26,4324.85 6141.87,4362.45 6141.87,4641.38 5562.04,4641.38 4546.49,4641.38 4525.19,4620.08 4525.19,3657.14 4631,3657.14 4631,4215 4795.61,4379.61
5V_IN_SW on PWR1 "PWR1-5V_IN_SW" (solid, remove dead copper, pour order 410): 5130.67,4363.47 5283.35,4516.16 5828.03,4516.16 5980.71,4363.47 6153.31,4363.47 6153.31,4641.38 6966,4641.38 6966,4318.3 7112.08,4318.3 7112.08,3657.08 6725.97,3655.06 6725.97,3945.7 6528.15,4143 5935.77,4143 5698.54,4380.23 5533.99,4380.23 5209.22,4055.46 4787.37,4055.46 4787.37,3656.75 4635,3656.75 4635,4205 4793.47,4363.47
no net on PWR1 "L4 PWR/GND-No Net" (solid, remove dead copper, pour order 380): 3990.62,3973.27
GND on Sig1 " " (solid, remove dead copper, pour order 683): 2584.58,4448.76 4380.91,4448.76 4380.91,3834.46 2584.58,3834.46
GND on Sig1 " " (solid, remove dead copper, pour order 511): 6973.04,4607.42 6991.7,4607.42 6991.7,4572.07 6970.58,4572.07 6970.58,4318.21 7112.34,4318.21 7112.34,3657.14 4513.77,3657.14 4513.77,4641.76 6973.04,4638.42
AR_1V8 on Sig1 " " (solid, remove dead copper, pour order 422): 3664.78,4031.89 3659.63,4026.74 3617.1,4026.74 3594.9,4004.54 3594.9,3985.07 3539.35,3929.53 3409.71,3929.53 3409.71,4008.82 3546.16,4145.27 3652.18,4145.27 3727.91,4221 3885.5,4221 3911.66,4194.84 3911.66,4055.2 3888.35,4031.89
PMICVIO_3V3 on Sig1 "Sig1-PMICVIO_3V3" (solid, remove dead copper, pour order 286): 3072.52,4084.47 3072.52,4160.22 3009.04,4223.7 3009.04,4299.44 3009.04,4377.87 2978.81,4408.1 2895.72,4408.1 2849.25,4361.64 2849.25,4267.86 2969.76,4147.35 2969.76,4019.52 3056.14,3933.14 3175.74,3933.14 3209.13,3966.53 3209.13,4026.48 3203.88,4031.72 3125.27,4031.72
3V0 on Sig1 "Sig1-3V0" (solid, remove dead copper, pour order 457): 6844.28,3827.94 6817.4,3854.82 6763.85,3854.82 6627.54,3991.13 6235.53,3991.13 6169.71,3925.31 6169.71,3854.82 6235.53,3854.82 6235.53,3779.52 6332.56,3781.06 6332.56,3931.53 6353.96,3952.93 6595.88,3952.93 6676.2,3872.61 6676.2,3688.85 6844.28,3688.85
no net on Sig1 "Sig1-No Net" (solid, remove dead copper, pour order 697): 4088.43,4327.31
no net on Sig1 "L3 SIG 1-No Net" (solid, remove dead copper, pour order 467): 3904.98,3968.25
GND on GND1 "GND1-GND" (solid, remove dead copper, pour order 358): 6970.88,4318.4 7112.08,4318.4 7112.08,3656.75 4522.29,3656.75 4522.29,3843 2584.59,3843 2585.01,4451.17 4522,4451.17 4522,4641.38 6971.07,4641.38
no net on GND1 "L6 SIG 2-No Net" (solid, remove dead copper, pour order 302): 4825.92,3926.28
no net on GND1 "DVDD_21MP_1V8_L08_P-001" (solid, remove dead copper, pour order 300): 3885.7,4256.64
GND on Sig2 " " (solid, remove dead copper, pour order 677): 2584.58,3835.08 2584.58,4448.76 3879.97,4448.76 3880.04,4344.3 3857.77,4322.03 3857.77,4309.88 3762.8,4214.91 3566.05,4214.91 3400.23,4049.09 3400.23,3833.89
PMIC_3V3 on Sig2 "Sig2-PMICOUT_3V3" (solid, remove dead copper, pour order 509): 3815.51,3963.78 3815.51,3897.91 3787.72,3870.12 3630.99,3870.12 3601.87,3899.24 3572.53,3899.24 3526.95,3944.82 3526.95,4087.66 3594.06,4154.77 3633.67,4154.77 3642.78,4145.66 3642.78,4083.12 3623.66,4064 3582.95,4023.29 3582.95,3976.83 3598.58,3961.21 3673.49,3961.21 3675.96,3963.68 3757,3963.68
AR_1V8 on Sig2 " " (solid, remove dead copper, pour order 418): 4163.44,4344.97 4163.44,4437.78 4159.6,4441.62 3857.52,4441.62 3805.52,4389.62 3701.42,4389.62 3600.61,4288.8 3474.76,4288.8 3415.49,4229.54 3415.49,3920.9 3514.26,3920.9 3514.26,4114.51 3643.85,4244.1 3749.28,4244.1 3788.56,4283.37 3837.78,4283.37 3882.93,4238.22 4163.44,4238.22
PMICVIO_3V3 on Sig2 " " (solid, remove dead copper, pour order 356): 3007.82,4443.69 3232.86,4443.69 3232.86,4286.17 3195.09,4248.4 3142.39,4248.4 3098.11,4292.69 3027.07,4292.69 3007.82,4271.83 3007.82,4249.69 2829.82,4249.69 2829.82,4443.69
GND on Sig2 " " (solid, remove dead copper, pour order 685): 3948.09,4059 3954.56,4052.53 4031.47,4052.53 4046,4038 4046,3978 4128.3,3978 4161.3,4011 4180,4011 4180,4251.36 4232,4303.36 4232,4353 3873,4353 3873,4059
GND on Sig2 " " (solid, remove dead copper, pour order 679): 6973.37,4606.18 6992.03,4606.18 6992.03,4570.83 6970.91,4570.83 6970.91,4316.97 7112.67,4316.97 7112.68,3655.9 4514.11,3655.9 4514.11,4640.52 6973.37,4637.18
GND on Sig2 "Sig2-GND" (solid, remove dead copper, pour order 455): 6403.37,3696.46
VCC_BA_3V3 on PWR2 "PWR2-VCC_BA_3V3" (solid, remove dead copper, pour order 695): 6970,4318.1 7112.08,4318.1 7112.08,3657.14 4514.14,3657.14 4514.15,4641.38 6970,4641.38
PMIC_3V3 on PWR2 " " (solid, remove dead copper, pour order 404): 3041.32,3913.7 3062.87,3935.25 3392.01,3935.25 3416.65,3910.62 3702.15,3910.62 3710.16,3902.61 3721.25,3891.52 3721.25,3849.27 3706.96,3834.98 2744.14,3834.98 2666.51,3912.62 2666.51,4400.08 2717.74,4451.32 2879.95,4451.32 2879.95,4453.77 3533.3,4453.77 4803.53,4453.77 4803.53,3925.05 4674.1,3925.05 4610.88,3988.27 4611.23,4071.6 4610.8,4095.62 4579.6,4126.82 4422.16,4126.82 4415.98,4133 4332.23,4133 4301.92,4163.3 4301.92,4208.35 4270.16,4240.11 4208.05,4302.22 3235.3,4302.23 3204.36,4271.28 3173.19,4240.11 2923.79,4240.11 2869.53,4294.38 2869.53,4322 2779.68,4322 2751.13,4293.46 2751.75,4292.84 2751.75,3998.54 2836.59,3913.7
5V_IN on PWR2 " " (solid, remove dead copper, pour order 487): 3531.38,4064.58 4083.76,4064.58 4142.82,4005.52 4153.58,3994.76 4193.24,3994.76 4229.16,3958.84 4262.42,3957.75 4286.21,3957.75 4322,3921.96 4322,3876.09 4353.26,3844.83 4413.43,3844.83 4439.46,3818.81 4453.67,3818.32 4514.15,3818.32 4514.15,3677.73 4743.98,3677.73 4743.98,3847.78 4597,3994.76 4597,4100 4573.8,4123.2 4462.7,4122.8 4327.06,4122.8 4302,4147.86 4302,4211.85 4271.3,4229.17 4211.04,4289.43 3741.35,4289.43 3245.11,4286.9 3187.39,4229.17 2910.12,4229.17 2856.12,4283.17 2856.12,4312.67 2781.52,4312.67 2781.52,3917.37 3281.18,3917.37 3370.33,3917.37 3392.42,3939.47 3392.42,4064.58
PMIC_3V3 on PWR2 "PWR2-PMIC_3V3" (solid, remove dead copper, pour order 382): 4015.37,3840.94 4015.85,3894.74 4030.51,3909.4 4167.69,3909.4 4201.64,3875.45 4201.64,3840.94
AR_1V8 on PWR2 "PWR2-VIOIN_1V8" (solid, remove dead copper, pour order 402): 3534.83,3931.25 3543.47,3939.89 3655.73,3939.89 3663.62,3931.25 3702.59,3931.25 3797.81,3836.04 3815.95,3836.38 4223.5,3836.38 4269.97,3836.6 4310.66,3877.29 4310.66,3918.2 4282.76,3946.1 4220.49,3946.1 4182.83,3983.77 4150.56,3983.77 4083.64,4052.78 3404.43,4052.78 3404.43,3931.25
VDDS on PWR2 "PWR2-VDDS" (solid, remove dead copper, pour order 406): 6200.92,4295.06 6283.81,4212.17 6427.22,4212.17 6460.14,4179.25 6582.31,4179.25 6582.96,4179.9 6582.96,3993.14 6529.78,3939.96 6208.12,3939.96 6134.69,4010.53 6134.69,4295.06
no net on PWR2 " " (solid, remove dead copper, pour order 485): 3419.66,3833.17
no net on Bottom Solder " " (solid): 3971.54,4114.95 3971.54,4089.54 4044.63,4016.38 4141,4016.38 4203.18,4016.38 4203.18,4228.57 3946.06,4228.57 3946.06,4124.94 3949.74,4121.26 3965.23,4121.26
no net on Bottom Solder " " (solid): 4441.36,3932.89 4426.11,3932.89 4407,3952 4407,4017.59 4430.02,4040.6 4509.91,4040.6 4517,4033.51 4517,4010.42 4514.12,4007.54 4514.12,3932.89
no net on Bottom Solder " " (solid, remove dead copper): 4514.15,4464.37
no net on Bottom Solder " " (solid): 4524.01,4436.06 4523.99,4070 4416,4070 4416,4149 4423,4156 4423,4272 4411.7,4283.3 4411.7,4436.06
no net on Bottom Solder " " (solid, remove dead copper): 4512,4464.37
no net on Top Overlay (solid, remove dead copper): 6039.68,3802.89
no net on Top Solder (solid): 4008,4261.97 3925,4261.97 3925,4185.97 4008,4185.97
no net on Top Solder (solid): 4008,4178.47 3925,4178.47 3925,4102.47 4008,4102.47
no net on Top Solder (solid): 4098.5,4178.47 4015.5,4178.47 4015.5,4102.47 4098.5,4102.47
no net on Top Solder (solid): 4189,4178.47 4106,4178.47 4106,4102.47 4189,4102.47
no net on Top Solder (solid): 4189,4261.97 4106,4261.97 4106,4185.97 4189,4185.97
no net on Top Solder (solid): 4098.5,4094.97 4015.5,4094.97 4015.5,4018.97 4098.5,4018.97
no net on Top Solder (solid): 4189,4094.97 4106,4094.97 4106,4018.97 4189,4018.97
no net on Top Solder (solid): 4098.5,4261.97 4015.5,4261.97 4015.5,4185.97 4098.5,4185.97
no net on Top Solder (solid): 4008,4094.97 3925,4094.97 3925,4018.97 4008,4018.97
no net on Top Paste (solid): 4008,4261.97 3925,4261.97 3925,4185.97 4008,4185.97
no net on Top Paste (solid): 4098.5,4261.97 4015.5,4261.97 4015.5,4185.97 4098.5,4185.97
no net on Top Paste (solid): 4189,4261.97 4106,4261.97 4106,4185.97 4189,4185.97
no net on Top Paste (solid): 4189,4178.47 4106,4178.47 4106,4102.47 4189,4102.47
no net on Top Paste (solid): 4098.5,4178.47 4015.5,4178.47 4015.5,4102.47 4098.5,4102.47
no net on Top Paste (solid): 4008,4178.47 3925,4178.47 3925,4102.47 4008,4102.47
no net on Top Paste (solid): 4008,4094.97 3925,4094.97 3925,4018.97 4008,4018.97
no net on Top Paste (solid): 4098.5,4094.97 4015.5,4094.97 4015.5,4018.97 4098.5,4018.97
no net on Top Paste (solid): 4189,4094.97 4106,4094.97 4106,4018.97 4189,4018.97
GND on GND2 "GND 3-GND" (solid, remove dead copper, pour order 310): 4911.96,3657.14 4914.51,3659.69 5113.76,3659.69 7112.34,3656.76 7112.34,4318.4 6973.55,4318.4 6973.55,4641.74 4522.77,4641.74 4522.77,4456.16 2584.41,4456.17 2584.58,3842.63 3017.74,3842.62 4514.15,3842.62 4514.15,3657.14

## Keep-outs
Keep-Out Layer:
  circle w1: c5014.62,3754.06 r118.11
  circle w1: c6425.96,3754.06 r118.11
  text ".Layer_Name" at 577,-858.49 h60

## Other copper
Top Layer:
  region net 5V_IN: 2998.12,4096.98 2998.32,4059.43 2961.33,4059.43 2961.33,4096.99
  region net 5V_IN: 3252.85,4058.98 3252.85,4096.99 3215.54,4096.98 3215.54,4058.98
  region net 5V_IN: 3215.79,4186.23 3215.79,4224.92 3252.65,4224.92 3252.65,4186.23
  pour cut-out: 5726.17,3364.19
  pour cut-out: 6426.98,3656.61
  pour cut-out: 6349.84,3665.07
  pour cut-out: 6425,3754.84
  pour cut-out: 6425,3754.84
  pour cut-out: 4579.91,4245.94 4580.07,4245.78 4594.27,4245.78 4605.79,4234.27 4605.79,4117.23 4601.22,4112.66 4578.26,4112.66 4559.91,4131.01 4559.91,4180.77 4579.91,4200.77 4577.85,4202.82 4577.85,4237.51
  pour cut-out: 4995.11,3883.55
  region: 6387.24,4234.62
  region: 6649.74,3895.26
  region: 4839.75,4312.54
  region: 4839.75,4312.54
  region: 4297.87,4030.14
  pour cut-out: 5188.37,4353.46
  text ".Layer_Name" at 577,-858.49 h60
GND1:
  pour cut-out: 6471.25,4572.06 ccw(c6471.24,4560.52) 6459.71,4560.52 6459.81,4555.37 6459.81,4512.37 6483.81,4488.37 6483.81,4299.36 6459.29,4275.06 6459.29,4231.85 6424.81,4231.84 6424.81,4267.04 6397.37,4295.04 6397.37,4484.62 6424.04,4511.28 6424.04,4551.88 cw(c6479.61,4551.88) 6479.61,4607.45 6492.81,4607.59 6991.81,4607.59 6991.81,4572.06
  pour cut-out: 7083.89,3879.91 7024.96,3879.91 7024.96,3830.25 7008.88,3814.16 7002.72,3814.16 6996.54,3820.35 6996.54,3846.37 6964.01,3878.9 6930.37,3878.9 6925.41,3883.86 6925.41,3904.5 6896.81,3904.5 6880.31,3888 6839.7,3888 6837.55,3885.85 6837.55,3845.38 6839.62,3843.31 6884.39,3843.31 6898.7,3829 6920.81,3829 6925.89,3834.07 6925.51,3848.95 6931.23,3854.68 6953.53,3854.68 6972.21,3836 6972.21,3809.94 6994.31,3787.84 7006.77,3787.84 7024.96,3769.65 7024.96,3722.9 7083.89,3722.9
  pour cut-out: 5907.4,4424.33 5891.48,4440.25 5891.48,4517.72 5844.55,4564.66 5844.55,4603.24 6000.51,4603.24 6000.51,4556.4 5960.28,4516.18 5960.28,4443.7 5940.63,4424.05
  text ".Layer_Name" at 577,-858.49 h60
Sig1:
  region net SPI_CLK1: 5119.06,3986.18
  pour cut-out: 3726.46,3918.57
  region: 5204.19,3821.28
  text ".Layer_Name" at 577,-858.49 h60
PWR1:
  text ".Layer_Name" at 577,-858.49 h60
PWR2:
  region: 4310.33,4474.56
  text ".Layer_Name" at 577,-858.49 h60
Sig2:
  text ".Layer_Name" at 577,-858.49 h60
GND2:
  pour cut-out: 5811.46,3712.67
  pour cut-out: 5908.96,3794.29
  text ".Layer_Name" at 577,-858.49 h60
Bottom Layer:
  pour cut-out: 6454.46,4049.83 6529.46,4049.83 6529.46,4031.83 6454.46,4031.83
  pour cut-out: 3777.9,4410.91
  pour cut-out: 3821.58,4412.09
  pour cut-out: 3626.65,4258.65 3782.66,4258.65 3782.66,4393.19 3626.65,4393.19
  region: 3626.27,4372.01
  pour cut-out: 5275.3,4441.85
  text ".Layer_Name" at 577,-858.49 h60

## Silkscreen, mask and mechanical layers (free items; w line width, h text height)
Top Overlay:
  drawing of 999 lines, arcs and shapes, not listed
  text "ANT" at 6997.07,4618.54 h15
  text "CAN1" at 5705.55,4605.09 h15
  text "CLK_P" at 5234.82,4604.14 h15
  text "USR_LED" at 4723.8,4599.7 h13
  text "CAN_H" at 5764.7,4557.59 h15
  text "CAN_L" at 6037.84,4552.76 h15 r90
  text "GND" at 5902.73,4526.81 h15
  text "3V3" at 4565.47,4510.99 h15
  text "3V3" at 4993.77,4507.43 h15 r90
  text "SCL" at 5044.6,4506.47 h15 r90
  text "GND" at 5148.17,4506.47 h15 r90
  text "60PIN" at 5461.3,4505.87 h15 r90
  text "SDA" at 5095.42,4503.6 h15 r90
  text "60PIN/BT" at 5407.96,4487.66 h15 r90
  text "LED" at 4572.72,4480.79 h15
  text "BT_JTAG_HDR" at 6192.49,4462.03 h15
  text "GND" at 5147.35,4408.25 h15 r90
  text "BT_LED" at 6209.33,4356.3 h15 r90
  text "GND" at 2609.25,4341.79 h15
  text "RST_LED" at 4924.72,4330.86 h15
  text "RST_SW" at 4806.25,4257.23 h15
  text "5V_LED" at 2627.26,4171.19 h15 r90
  text "'.PRJ_Number'" at 5711.96,4171.09 h25
  text "USB2" at 6844.66,4170.59 h15
  text "REV. G" at 5807.21,4131.37 h25
  text "CAN" at 5202.96,4125.61 h15 r90
  text "'.PRJ_Number'" at 2540.61,4117.61 h25
  text "60PIN" at 5257.16,4116.94 h15 r90
  text "BT_EN" at 5300.52,4106.1 h15 r90
  text "REV. G" at 2609.58,4087.96 h25
  text "LCD_DISP2" at 4703.55,4054.67 h15 r90
  text "SOP1" at 5584.9,4044.61 h15 r90
  text "USB_LED" at 3543.43,4026.73 h15 r90
  text "BT" at 5464.57,4027.24 h15 r90
  text "SOP0" at 5510.56,4024.92 h15 r90
  text "CP2105" at 5434.17,4011.23 h15 r90
  text "USR_SW" at 5002.04,3986.13 h15 r90
  text "3V3" at 3683.43,3929.39 h15
  text "CAN2" at 6954.08,3909.14 h15
  text "LCD_DISP1" at 5564.31,3865.44 h15
  text "CAN_H" at 6948.02,3859.04 h15
  text "GND" at 7016.85,3788.56 h15 r90
  text "BT_DIS" at 5331.39,3700.83 h15
  text "BT/LCD" at 5214.43,3697.87 h15
  text "SPI" at 5198.89,3696.39 h15 r90
  text "CAN_L" at 7004.9,3690.6 h15
  text ".Layer_Name" at 557.88,-855.15 h60
Bottom Overlay:
  drawing of 55 lines, arcs and shapes, not listed
  text "ICBOOST_CONN" at 4869.23,4600.01 h25
  text "S/N:" at 7054.26,4555.33 h40
  text "OPN:" at 7053.04,4398.05 h40
  text "For evaluation only;" at 6904.33,4270.31 h30
  text "not FCC approved for resale." at 6905.33,4220.31 h30
  text "DCA_CONN" at 5640.1,4006.84 h25 r270
  text "USB1" at 2746.49,3972.62 h15
  text "S3" at 4291.19,3882.87 h25 r270
  text "SOP2" at 4443.82,3859.98 h15 r270
  text "U14" at 6251.17,3699.28 h30
  text ".Layer_Name" at 577,-858.49 h15
Top Paste:
  text ".Layer_Name" at 577,-858.49 h60
Bottom Paste:
  text ".Layer_Name" at 577,-858.49 h60
Top Solder:
  text ".Layer_Name" at 577,-858.49 h60
  text ".Layer_Name" at 577,-858.49 h60
Bottom Solder:
  text ".Layer_Name" at 577,-858.49 h60
Drill Guide:
  text ".Layer_Name" at 577,-858.49 h60
M1 Board Outline:
  lines w10: 2584.27,3882.46 ccw(c2632.27,3882.46) 2632.27,3834.46 4466.14,3834.46 cw(c4466.14,3786.46) 4514.14,3786.46 4514.14,3705.09 ccw(c4562.14,3705.09) 4562.14,3657.09 ; 2584.27,4588.76 ccw(c2632.27,4588.76) 2632.27,4540.76 ; 2584.58,4401.07 cw(c2632.58,4401.07) 2632.58,4449.07 ; 2584.58,4588.76 2584.58,4882.46 cw(c2632.58,4882.46) 2632.58,4930.46 7064.34,4930.46 cw(c7064.34,4882.46) 7112.34,4882.46 7112.34,4781.61 cw(c7064.34,4781.61) 7064.34,4733.61 ; 2632.58,3741.94 ccw(c2632.58,3693.94) 2584.58,3693.94 2584.58,3415.85 ccw(c2632.58,3415.85) 2632.58,3367.85 7064.03,3367.89 ; 2632.58,4448.76 4466.15,4448.76 ccw(c4466.15,4496.76) 4514.15,4496.76 4514.15,4593.74 cw(c4562.15,4593.74) 4562.15,4641.74 ; 2632.58,4540.76 4374.12,4540.76 ; 2635,3741.94 4374.14,3741.94 ; 4374.14,3741.99 cw(c4374.14,3693.99) 4422.14,3693.99 4422.14,3612.62 ccw(c4470.14,3612.62) 4470.14,3564.62 ; 4374.15,4540.76 ccw(c4374.15,4588.76) 4422.15,4588.76 4422.15,4685.74 cw(c4470.15,4685.74) 4470.15,4733.74 ; 4470.15,4733.7 4854.56,4733.65 ccw(c4854.56,4781.65) 4902.56,4781.65 4902.56,4789.98 cw(c4950.56,4789.98) 4950.56,4837.98 6412.61,4837.98 cw(c6412.61,4789.98) 6460.61,4789.98 6460.61,4781.65 ccw(c6508.61,4781.65) 6508.61,4733.65 7064.34,4733.7 ; 4471.44,3564.65 7064.03,3564.65 cw(c7064.03,3516.65) 7112.03,3516.65 7112.03,3415.8 cw(c7064.03,3415.8) 7064.03,3367.8 ; 4562.14,3657.14 7064.03,3657.14 ; 4562.15,4641.7 7064.34,4641.38 ; 7064.08,3656.83 ccw(c7064.08,3704.83) 7112.08,3704.83 ; 7064.34,4641.47 cw(c7064.34,4593.47) 7112.34,4593.47 7112.34,3704.83 ; 4441.36,3957.89 ccw(c4466.36,3957.89) 4466.36,3932.89 4489.12,3932.89 ; 4441.36,3957.89 4441.36,3957.89 ; 4441.36,3957.89 4441.36,3982.54 cw(c4466.36,3982.54) 4466.36,4007.54 ; 4441.37,4316.3 ccw(c4466.37,4316.3) 4466.37,4291.3 4489.13,4291.3 ; 4441.37,4316.3 4441.37,4316.3 ; 4441.37,4316.3 4441.37,4340.95 cw(c4466.37,4340.95) 4466.37,4365.95 ; 4466.36,4007.54 4489.12,4007.54 cw(c4489.12,3982.54) 4514.12,3982.54 4514.12,3957.89 cw(c4489.12,3957.89) 4489.12,3932.89 ; 4466.36,4007.54 4466.36,4007.54 ; 4466.36,4106.32 cw(c4466.36,4131.32) 4441.36,4131.32 4441.36,4160.46 cw(c4466.36,4160.46) 4466.36,4185.46 4489.13,4185.46 ; 4466.36,4106.32 4466.36,4106.32 ; 4466.36,4106.32 4489.13,4106.32 ccw(c4489.13,4131.32) 4514.13,4131.32 4514.13,4160.46 ccw(c4489.13,4160.46) 4489.13,4185.46 ; 4466.37,4365.95 4466.37,4365.95 ; 4466.37,4365.95 4489.13,4365.95 cw(c4489.13,4340.95) 4514.13,4340.95 4514.13,4316.3 cw(c4489.13,4316.3) 4489.13,4291.3 ; 4489.12,3932.89 4489.12,3932.89 ; 4489.13,4185.46 4489.13,4185.46 ; 4489.13,4291.3 4489.13,4291.3 ; 2584.58,3882.46 2584.58,4400.76 2584.58,3882.46 ; 4514.15,4554.37 4514.15,4554.37
M2 Board Dimensions:
  text "X3" at 4261,4078 h60 r90
  text "X3" at 4593,3426 h60
  text "X24" at 7582.02,3284.3 h60
  text "X12" at 3883,3246 h60
  text "M2 Board Dimensions" at 577,-858.49 h60
M3 3D STEP Top:
  text ".Layer_Name" at 577,-858.49 h60
M4 3D STEP Bottom:
  text ".Layer_Name" at 577,-858.49 h60
M5 Assembly Top:
  lines w4: 2861.82,4216.17 2861.82,4223.73 ; 2863.87,4097.94 2863.88,4097.93 2863.88,4093.14 ; 2880.38,4175.62 2880.38,4172.18 2883.82,4168.74 ; 3689.74,4371.19 3694.98,4371.19 3715.95,4350.23 ; 6230.28,4361.97 6262.56,4361.97 6263.13,4361.4
  lines w6: 3133.38,3862.46 3133.38,3882.61 3149.2,3898.43 3170.81,3898.43 ; 3623.4,4195.91 3623.4,4223.72 3647.03,4247.35 3674.85,4247.35 ; 4662.35,4264.72 4670.99,4256.08 4670.99,4274.35 4662.35,4265.7 ; 5613.16,3814.77 5604.52,3823.41 5622.78,3823.41 5614.14,3814.77 ; 6001.66,4578.71 5993.02,4570.07 6011.28,4570.07 6002.64,4578.71 ; 6365,4569.61 6356.36,4560.97 6374.62,4560.97 6365.98,4569.61 ; 3674.85,4247.35 3674.85,4247.35 ; 4831.35,4121.85 4849.61,4121.85 4840.97,4130.49 4839.99,4130.49 4831.35,4121.85 ; 6915.37,4096.97 6924.01,4105.61 6924.01,4106.59 6915.37,4115.23 6915.37,4096.97 ; 7026.96,3739.75 7035.6,3748.39 7035.6,3749.37 7026.96,3758.01 7026.96,3739.75
  lines w10: -287.5,-917.17 6312.5,-917.17 ; -287.5,-713.83 6314.5,-713.83 ; -287.5,-510.5 -287.5,-1120.5 3717.5,-1120.5 6314.5,-1120.5 6314.5,-510.5 -287,-510.5 -287,-1120.5 1288.5,-1120.5 ; 2177.5,-1120.5 2177.5,-510.5 ; 3444.5,-713.83 3444.5,-510.5 ; 4284.5,-713.83 4284.5,-510.5 ; 4906.5,-1127 4906.5,-924.17
  text "A" at 3622.6,4245.24 h20
  text "A" at 3113.22,3895.99 h20
  text "COMPONENTS MARKED 'DNP' SHOULD NOT BE POPULATED." at -159.85,-299.74 h60
  text "ASSEMBLY VARIANT:" at -160.35,-415.24 h60
  text ".VariantName" at 875.65,-415.24 h60
  text "PCB VIEWED FROM TOP SIDE" at -228.5,-655.67 h60
  text "BOARD #:" at 2248,-655.67 h60
  text ".PRJ_Number" at 2793.5,-655.67 h60
  text "REV:" at 3638,-655.67 h60
  text ".PCB_Rev" at 3929.5,-655.67 h60
  text "SVN REV:" at 4476,-655.67 h60
  text ".VersionControl_RevNumber" at 4982,-655.67 h60
  text ".Layer_Name" at 538.89,-854.26 h60
  text "TID #:" at 2248,-859 h60
  text ".TID" at 2793.5,-859 h60
  text "PLOT NAME =" at -228.5,-1064.34 h60
  text ".plot_File_Name" at 577,-1064.34 h60
  text "GENERATED    :" at 2250,-1064.34 h60
  text ".Print_Date" at 3119.5,-1064.34 h60
  text ".Print_Time" at 3848.5,-1064.34 h60
  text "TEXAS INSTRUMENTS" at 5113,-1064.34 h60
M6 Assembly Bottom:
  lines w4: 3773.16,3978.38 3773.4,3978.62 3773.4,3989.15 ; 3819.36,3990.79 3824.34,3995.77 ; 3843.86,4392.47 3843.86,4395.52 3843.85,4395.53 ; 3881.66,4354.6 3881.66,4357.89
  lines w6: 2763.12,4114.67 2771.76,4106.03 2771.76,4124.3 2763.12,4115.65 ; 3587.59,4401.78 3629.1,4401.78 3662.06,4434.74 3747.34,4434.74 ; 3781.64,4339.24 3790.28,4330.6 3790.28,4348.86 3781.64,4340.22 ; 3795.36,4433.75 4185.67,4433.75 ; 4180.08,4440 4185.67,4434.41 ; 4180.73,4428.74 4185.67,4433.68 ; 4239.2,4158.05 4252.49,4144.77 ; 4243.93,4144.77 4252.49,4144.77 ; 4252.49,4153.32 4252.49,4144.77 ; 4419.7,4180.85 4432.98,4194.13 ; 4424.41,4117.33 4437.7,4104.04 ; 4424.43,4194.13 4432.98,4194.13 ; 4429.14,4104.04 4437.7,4104.04 ; 4432.98,4185.58 4432.98,4194.13 ; 4437.7,4112.6 4437.7,4104.04 ; 4561.7,3858.19 4553.06,3849.55 4553.06,3867.81 4561.7,3859.17 ; 4987.75,4561.05 4979.11,4552.41 4997.38,4552.41 4988.73,4561.05 ; 5180.73,3836.94 5172.09,3828.3 5172.09,3846.56 5180.73,3837.92 ; 6061.02,4378.57 6069.66,4369.93 6069.66,4388.2 6061.02,4379.56 ; 6845.58,3917.61 6836.94,3926.25 6855.2,3926.25 6846.56,3917.61
  lines w10: -288,-714.33 6314,-714.33 ; -286,-917.67 6314,-917.67 ; 1120,-1127.5 1120,-924.67 ; 1742,-714.33 1742,-511 ; 2582,-714.33 2582,-511 ; 3849,-1121 3849,-511 ; 4738,-1121 6313.5,-1121 6313.5,-511 -288,-511 -288,-1121 2309,-1121 6314,-1121 6314,-511
  text "COMPONENTS MARKED 'DNP' SHOULD NOT BE POPULATED." at 6102,-318 h60
  text ".VariantName" at 5058,-434 h60
  text "ASSEMBLY VARIANT:" at 6097,-434 h60
  text ".VersionControl_RevNumber" at 1035.5,-656.17 h60
  text "SVN REV:" at 1541.5,-656.17 h60
  text ".PCB_Rev" at 2088,-656.17 h60
  text "REV:" at 2379.5,-656.17 h60
  text ".PRJ_Number" at 3224,-656.17 h60
  text "BOARD #:" at 3769.5,-656.17 h60
  text "PCB VIEWED FROM BOTTOM SIDE" at 6246,-656.17 h60
  text ".Layer_Name" at 1514.22,-848.89 h60
  text ".TID" at 3224,-859.5 h60
  text "TID #:" at 3769.5,-859.5 h60
  text "TEXAS INSTRUMENTS" at 904.5,-1064.84 h60
  text ".Print_Time" at 2169,-1064.84 h60
  text ".Print_Date" at 2898,-1064.84 h60
  text "GENERATED    :" at 3767.5,-1064.84 h60
  text ".plot_File_Name" at 5440.5,-1064.84 h60
  text "PLOT NAME =" at 6246,-1064.84 h60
